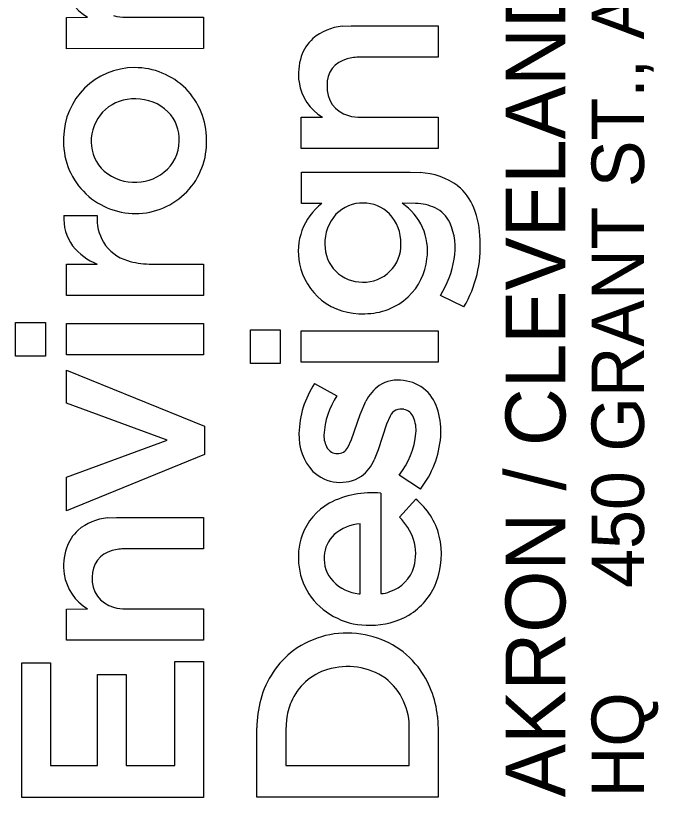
# Model space of a CAD drawing. Extents: x -13.5 to 34, y 0 to 22.
# Drawn here: x 32.377 to 32.989, y 3.138 to 3.882 of the extents above; entities that cross this region are included whole.
import ezdxf

# ---------------------------------------------------------------- set-up
doc = ezdxf.new("R2010")
doc.units = 0
doc.layers.add('RW_X_CL_100_Bearings', color=7, linetype='Continuous')

msp = doc.modelspace()

# ---------------------------------------------------------------- linework, layer by layer
at = {"layer": 'RW_X_CL_100_Bearings'}
for p, q in [((32.42542, 3.88066), (32.44552, 3.88071)), ((32.42542, 3.85086), (32.42542, 3.88066)), ((32.48222, 3.88071), (32.55569, 3.88071)), ((32.55569, 3.88071), (32.55571, 3.85096)), ((32.68784, 3.8722), (32.69634, 3.87266)), ((32.69634, 3.87266), (32.77916, 3.87266)), ((32.77916, 3.87266), (32.77917, 3.84287)), ((32.55571, 3.85096), (32.42542, 3.85086)), ((32.77917, 3.84287), (32.70485, 3.8428)), ((32.64888, 3.7855), (32.66897, 3.78555)), ((32.64888, 3.75569), (32.64888, 3.7855)), ((32.70568, 3.78555), (32.77915, 3.78555)), ((32.77915, 3.78555), (32.77917, 3.75579)), ((32.77917, 3.75579), (32.64888, 3.75569)), ((32.6489, 3.70336), (32.64889, 3.73322)), ((32.64889, 3.73322), (32.75236, 3.73322)), ((32.75236, 3.73322), (32.76191, 3.73285)), ((32.66836, 3.70336), (32.6489, 3.70336)), ((32.75763, 3.70356), (32.74487, 3.70361)), ((32.42299, 3.69193), (32.45454, 3.69193)), ((32.42542, 3.64577), (32.45473, 3.64579)), ((32.42542, 3.61593), (32.42542, 3.64577)), ((32.50413, 3.64581), (32.55571, 3.64573)), ((32.55571, 3.64573), (32.55565, 3.61593)), ((32.55565, 3.61593), (32.42542, 3.61593)), ((32.8036, 3.60491), (32.7812, 3.61598)), ((32.37705, 3.55818), (32.37705, 3.59026)), ((32.37705, 3.59026), (32.40543, 3.59026)), ((32.40543, 3.59026), (32.40543, 3.55818)), ((32.42542, 3.55942), (32.42542, 3.58928)), ((32.42542, 3.58928), (32.55571, 3.58928)), ((32.55571, 3.58928), (32.55571, 3.55942)), ((32.60051, 3.55111), (32.60051, 3.58319)), ((32.60051, 3.58319), (32.62889, 3.58319)), ((32.62889, 3.58319), (32.62889, 3.55111)), ((32.64888, 3.55234), (32.64888, 3.5822)), ((32.64888, 3.5822), (32.77917, 3.5822)), ((32.77917, 3.5822), (32.77917, 3.55234)), ((32.55571, 3.55942), (32.42542, 3.55942)), ((32.40543, 3.55818), (32.37705, 3.55818)), ((32.62889, 3.55111), (32.60051, 3.55111)), ((32.77917, 3.55234), (32.64888, 3.55234)), ((32.42542, 3.51327), (32.42542, 3.5446)), ((32.42542, 3.5446), (32.5567, 3.4913)), ((32.66151, 3.53207), (32.68268, 3.52025)), ((32.70483, 3.50258), (32.71036, 3.51526)), ((32.52117, 3.47798), (32.42542, 3.51327)), ((32.69675, 3.47868), (32.70483, 3.50258)), ((32.73342, 3.50101), (32.72985, 3.4933)), ((32.5567, 3.4913), (32.5567, 3.46441)), ((32.72985, 3.4933), (32.72213, 3.46882)), ((32.42542, 3.44294), (32.52117, 3.47798)), ((32.69299, 3.47117), (32.69675, 3.47868)), ((32.5567, 3.46441), (32.42542, 3.41086)), ((32.72213, 3.46882), (32.71822, 3.45921)), ((32.42542, 3.41086), (32.42542, 3.44294)), ((32.76214, 3.43141), (32.74198, 3.44469)), ((32.72453, 3.42747), (32.72463, 3.33195)), ((32.74228, 3.40465), (32.75768, 3.422)), ((32.46439, 3.40397), (32.47289, 3.40443)), ((32.47289, 3.40443), (32.55571, 3.40443)), ((32.55571, 3.40443), (32.55571, 3.37465)), ((32.70489, 3.33182), (32.70489, 3.39834)), ((32.55571, 3.37465), (32.4814, 3.37457)), ((32.70361, 3.33165), (32.70489, 3.33182)), ((32.42542, 3.31728), (32.44552, 3.31733)), ((32.42542, 3.28747), (32.42542, 3.31728)), ((32.48222, 3.31733), (32.55569, 3.31733)), ((32.55569, 3.31733), (32.55571, 3.28756)), ((32.55571, 3.28756), (32.42542, 3.28747)), ((32.38298, 3.13791), (32.38298, 3.26598)), ((32.38298, 3.26598), (32.41012, 3.26598)), ((32.41012, 3.26598), (32.41012, 3.16827)), ((32.52857, 3.16827), (32.52857, 3.26722)), ((32.52857, 3.26722), (32.55571, 3.26722)), ((32.55571, 3.26722), (32.55571, 3.13791)), ((32.45503, 3.16827), (32.45503, 3.25488)), ((32.45503, 3.25488), (32.48218, 3.25488)), ((32.48218, 3.25488), (32.48218, 3.16827)), ((32.63465, 3.21178), (32.63407, 3.2023)), ((32.77847, 3.21497), (32.77917, 3.2021)), ((32.60643, 3.13799), (32.60644, 3.204)), ((32.63407, 3.2023), (32.63407, 3.16838)), ((32.75149, 3.16834), (32.75153, 3.20239)), ((32.77917, 3.2021), (32.77917, 3.138)), ((32.41012, 3.16827), (32.45503, 3.16827)), ((32.48218, 3.16827), (32.52857, 3.16827)), ((32.63407, 3.16838), (32.75149, 3.16834)), ((32.55571, 3.13791), (32.38298, 3.13791)), ((32.77917, 3.138), (32.60643, 3.13799))]:
    msp.add_line(p, q, dxfattribs=at)
for points in [[(32.42542, 3.85086), (32.42542, 3.88066), (32.44552, 3.88071)], [(32.48222, 3.88071), (32.55569, 3.88071), (32.55571, 3.85096), (32.42542, 3.85086)], [(32.68784, 3.8722), (32.69634, 3.87266), (32.77916, 3.87266), (32.77917, 3.84287), (32.70485, 3.8428)], [(32.64888, 3.75569), (32.64888, 3.7855), (32.66897, 3.78555)], [(32.70568, 3.78555), (32.77915, 3.78555), (32.77917, 3.75579), (32.64888, 3.75569)], [(32.66836, 3.70336), (32.6489, 3.70336), (32.64889, 3.73322), (32.75236, 3.73322), (32.76191, 3.73285)], [(32.75763, 3.70356), (32.74487, 3.70361)], [(32.42299, 3.69193), (32.45454, 3.69193)], [(32.50413, 3.64581), (32.55571, 3.64573), (32.55565, 3.61593), (32.42542, 3.61593)], [(32.42542, 3.61593), (32.42542, 3.64577), (32.45473, 3.64579)], [(32.8036, 3.60491), (32.7812, 3.61598)], [(32.66151, 3.53207), (32.68268, 3.52025)], [(32.69299, 3.47117), (32.69675, 3.47868), (32.70483, 3.50258), (32.71036, 3.51526)], [(32.73342, 3.50101), (32.72985, 3.4933), (32.72213, 3.46882), (32.71822, 3.45921)], [(32.76214, 3.43141), (32.74198, 3.44469)], [(32.72453, 3.42747), (32.72463, 3.33195)], [(32.74228, 3.40465), (32.75768, 3.422)], [(32.46439, 3.40397), (32.47289, 3.40443), (32.55571, 3.40443), (32.55571, 3.37465), (32.4814, 3.37457)], [(32.70361, 3.33165), (32.70489, 3.33182), (32.70489, 3.39834)], [(32.42542, 3.28747), (32.42542, 3.31728), (32.44552, 3.31733)], [(32.48222, 3.31733), (32.55569, 3.31733), (32.55571, 3.28756), (32.42542, 3.28747)], [(32.77847, 3.21497), (32.77917, 3.2021), (32.77917, 3.138), (32.60643, 3.13799)], [(32.63465, 3.21178), (32.63407, 3.2023), (32.63407, 3.16838), (32.75149, 3.16834), (32.75153, 3.20239)], [(32.60643, 3.13799), (32.60644, 3.204)]]:
    msp.add_lwpolyline(points, dxfattribs=at)
for points in [[(32.37705, 3.55818), (32.37705, 3.59026), (32.40543, 3.59026), (32.40543, 3.55818)], [(32.42542, 3.55942), (32.42542, 3.58928), (32.55571, 3.58928), (32.55571, 3.55942)], [(32.60051, 3.55111), (32.60051, 3.58319), (32.62889, 3.58319), (32.62889, 3.55111)], [(32.64888, 3.55234), (32.64888, 3.5822), (32.77917, 3.5822), (32.77917, 3.55234)], [(32.42542, 3.41086), (32.42542, 3.44294), (32.52117, 3.47798), (32.42542, 3.51327), (32.42542, 3.5446), (32.5567, 3.4913), (32.5567, 3.46441)], [(32.38298, 3.13791), (32.38298, 3.26598), (32.41012, 3.26598), (32.41012, 3.16827), (32.45503, 3.16827), (32.45503, 3.25488), (32.48218, 3.25488), (32.48218, 3.16827), (32.52857, 3.16827), (32.52857, 3.26722), (32.55571, 3.26722), (32.55571, 3.13791)]]:
    msp.add_lwpolyline(points, close=True, dxfattribs=at)
for centre, radius, start, end in [((32.47027, 3.92141), 0.04763, 188.96462, 238.69865), ((32.47027, 3.92141), 0.04763, 188.96462, 238.69865), ((32.48183, 3.92286), 0.04215, 254.08913, 270.52838), ((32.48183, 3.92286), 0.04215, 254.08913, 270.52838), ((32.69216, 3.82251), 0.04988, 94.97056, 130.22484), ((32.69216, 3.82251), 0.04988, 94.97056, 130.22484), ((32.68694, 3.83085), 0.04016, 132.22383, 161.68229), ((32.68694, 3.83085), 0.04016, 132.22383, 161.68229), ((32.70217, 3.82642), 0.05602, 162.27398, 187.79173), ((32.70217, 3.82642), 0.05602, 162.27398, 187.79173), ((32.70453, 3.79679), 0.04601, 89.60515, 105.33026), ((32.70453, 3.79679), 0.04601, 89.60515, 105.33026), ((32.69828, 3.81689), 0.02498, 103.68683, 182.21395), ((32.69828, 3.81689), 0.02498, 103.68683, 182.21395), ((32.49014, 3.76543), 0.0674, 89.84756, 179.64047), ((32.49014, 3.76543), 0.0674, 89.84756, 179.64047), ((32.49057, 3.76474), 0.0681, 359.54009, 90.21138), ((32.49057, 3.76474), 0.0681, 359.54009, 90.21138), ((32.69372, 3.82624), 0.04763, 188.96462, 238.69865), ((32.69372, 3.82624), 0.04763, 188.96462, 238.69865), ((32.7008, 3.81381), 0.02757, 175.58441, 255.13816), ((32.7008, 3.81381), 0.02757, 175.58441, 255.13816), ((32.48923, 3.76263), 0.0404, 87.04809, 175.57259), ((32.48923, 3.76263), 0.0404, 87.04809, 175.57259), ((32.49204, 3.75999), 0.04299, 45.84264, 90.98008), ((32.49204, 3.75999), 0.04299, 45.84264, 90.98008), ((32.49458, 3.76421), 0.03821, 357.88569, 44.15902), ((32.49458, 3.76421), 0.03821, 357.88569, 44.15902), ((32.70529, 3.82769), 0.04215, 254.08913, 270.52838), ((32.70529, 3.82769), 0.04215, 254.08913, 270.52838), ((32.49083, 3.76209), 0.06819, 176.8344, 270.40384), ((32.49083, 3.76209), 0.06819, 176.8344, 270.40384), ((32.48729, 3.7625), 0.03848, 175.15378, 221.14706), ((32.48729, 3.7625), 0.03848, 175.15378, 221.14706), ((32.49123, 3.76139), 0.06749, 270.06243, 2.37759), ((32.49123, 3.76139), 0.06749, 270.06243, 2.37759), ((32.49446, 3.76318), 0.0383, 308.28936, 359.43468), ((32.49446, 3.76318), 0.0383, 308.28936, 359.43468), ((32.48919, 3.76607), 0.04228, 223.09994, 268.80895), ((32.48919, 3.76607), 0.04228, 223.09994, 268.80895), ((32.49096, 3.7679), 0.04418, 266.56515, 308.06078), ((32.49096, 3.7679), 0.04418, 266.56515, 308.06078), ((32.75907, 3.66789), 0.06503, 53.40344, 87.49062), ((32.75907, 3.66789), 0.06503, 53.40344, 87.49062), ((32.76517, 3.68039), 0.05141, 21.60748, 50.5577), ((32.76517, 3.68039), 0.05141, 21.60748, 50.5577), ((32.70292, 3.65813), 0.05692, 127.37482, 192.22468), ((32.70292, 3.65813), 0.05692, 127.37482, 192.22468), ((32.70693, 3.66927), 0.0346, 88.47302, 136.42562), ((32.70693, 3.66927), 0.0346, 88.47302, 136.42562), ((32.70814, 3.66963), 0.03424, 44.27195, 90.47623), ((32.70814, 3.66963), 0.03424, 44.27195, 90.47623), ((32.71421, 3.65829), 0.05472, 352.1125, 55.92295), ((32.71421, 3.65829), 0.05472, 352.1125, 55.92295), ((32.75666, 3.65725), 0.04633, 65.01687, 88.8011), ((32.75666, 3.65725), 0.04633, 65.01687, 88.8011), ((32.71141, 3.66602), 0.0401, 137.46739, 182.33237), ((32.71141, 3.66602), 0.0401, 137.46739, 182.33237), ((32.70368, 3.666), 0.03996, 358.57141, 43.53765), ((32.70368, 3.666), 0.03996, 358.57141, 43.53765), ((32.7626, 3.67155), 0.03085, 26.26808, 63.80301), ((32.7626, 3.67155), 0.03085, 26.26808, 63.80301), ((32.73069, 3.66714), 0.08835, 1.15143, 21.3627), ((32.73069, 3.66714), 0.08835, 1.15143, 21.3627), ((32.46616, 3.68882), 0.04329, 175.87313, 216.34747), ((32.46616, 3.68882), 0.04329, 175.87313, 216.34747), ((32.50087, 3.68948), 0.04639, 176.9688, 209.60636), ((32.50087, 3.68948), 0.04639, 176.9688, 209.60636), ((32.73565, 3.66154), 0.05953, 349.30734, 23.43071), ((32.73565, 3.66154), 0.05953, 349.30734, 23.43071), ((32.47466, 3.69716), 0.05511, 218.09809, 248.7907), ((32.47466, 3.69716), 0.05511, 218.09809, 248.7907), ((32.49514, 3.68814), 0.04079, 211.94466, 253.2028), ((32.49514, 3.68814), 0.04079, 211.94466, 253.2028), ((32.70645, 3.6637), 0.03511, 178.88208, 271.08374), ((32.70645, 3.6637), 0.03511, 178.88208, 271.08374), ((32.70818, 3.66404), 0.03546, 268.27882, 1.55016), ((32.70818, 3.66404), 0.03546, 268.27882, 1.55016), ((32.70538, 3.66244), 0.11383, 329.6388, 3.25998), ((32.70538, 3.66244), 0.11383, 329.6388, 3.25998), ((32.50465, 3.7165), 0.07069, 252.46555, 269.57296), ((32.50465, 3.7165), 0.07069, 252.46555, 269.57296), ((32.70988, 3.65708), 0.05887, 313.74196, 353.8554), ((32.70988, 3.65708), 0.05887, 313.74196, 353.8554), ((32.70738, 3.66334), 0.08771, 327.31495, 351.57478), ((32.70738, 3.66334), 0.08771, 327.31495, 351.57478), ((32.70463, 3.65696), 0.05837, 190.75182, 231.28919), ((32.70463, 3.65696), 0.05837, 190.75182, 231.28919), ((32.70632, 3.66112), 0.06269, 232.46061, 272.59022), ((32.70632, 3.66112), 0.06269, 232.46061, 272.59022), ((32.70954, 3.65901), 0.06051, 269.6361, 312.70877), ((32.70954, 3.65901), 0.06051, 269.6361, 312.70877), ((32.73636, 3.48258), 0.08973, 146.53104, 178.7571), ((32.73636, 3.48258), 0.08973, 146.53104, 178.7571), ((32.74661, 3.49713), 0.04053, 125.51182, 153.41595), ((32.74661, 3.49713), 0.04053, 125.51182, 153.41595), ((32.7406, 3.5026), 0.03263, 80.17192, 122.51969), ((32.7406, 3.5026), 0.03263, 80.17192, 122.51969), ((32.74278, 3.49824), 0.03667, 47.79344, 84.68918), ((32.74278, 3.49824), 0.03667, 47.79344, 84.68918), ((32.73788, 3.4946), 0.04267, 14.9966, 46.20632), ((32.73788, 3.4946), 0.04267, 14.9966, 46.20632), ((32.74519, 3.4789), 0.07495, 146.51121, 176.91007), ((32.74519, 3.4789), 0.07495, 146.51121, 176.91007), ((32.74384, 3.49631), 0.01143, 76.66094, 155.7053), ((32.74384, 3.49631), 0.01143, 76.66094, 155.7053), ((32.74397, 3.49511), 0.01256, 21.5098, 78.52618), ((32.74397, 3.49511), 0.01256, 21.5098, 78.52618), ((32.72592, 3.48766), 0.03209, 354.57264, 22.06805), ((32.72592, 3.48766), 0.03209, 354.57264, 22.06805), ((32.71044, 3.48674), 0.07121, 355.83062, 15.39138), ((32.71044, 3.48674), 0.07121, 355.83062, 15.39138), ((32.69666, 3.48238), 0.05005, 177.53659, 222.79318), ((32.69666, 3.48238), 0.05005, 177.53659, 222.79318), ((32.68248, 3.49149), 0.0757, 321.81101, 354.79685), ((32.68248, 3.49149), 0.0757, 321.81101, 354.79685), ((32.6931, 3.48233), 0.02276, 178.47474, 211.08679), ((32.6931, 3.48233), 0.02276, 178.47474, 211.08679), ((32.68952, 3.4882), 0.09219, 321.9777, 355.87384), ((32.68952, 3.4882), 0.09219, 321.9777, 355.87384), ((32.68331, 3.4767), 0.01148, 212.23676, 268.37769), ((32.68331, 3.4767), 0.01148, 212.23676, 268.37769), ((32.68342, 3.47589), 0.01067, 267.71603, 333.73375), ((32.68342, 3.47589), 0.01067, 267.71603, 333.73375), ((32.68098, 3.4758), 0.04077, 308.08772, 335.98736), ((32.68098, 3.4758), 0.04077, 308.08772, 335.98736), ((32.68599, 3.47535), 0.0375, 225.98539, 302.47965), ((32.68599, 3.47535), 0.0375, 225.98539, 302.47965), ((32.7152, 3.34414), 0.08384, 83.61499, 118.28755), ((32.7152, 3.34414), 0.08384, 83.61499, 118.28755), ((32.70239, 3.36906), 0.05583, 118.83082, 160.62438), ((32.70239, 3.36906), 0.05583, 118.83082, 160.62438), ((32.71744, 3.37167), 0.06443, 13.53365, 51.36148), ((32.71744, 3.37167), 0.06443, 13.53365, 51.36148), ((32.46871, 3.35428), 0.04988, 94.96958, 130.22249), ((32.46871, 3.35428), 0.04988, 94.96958, 130.22249), ((32.70378, 3.36556), 0.05486, 19.03571, 45.44059), ((32.70378, 3.36556), 0.05486, 19.03571, 45.44059), ((32.70785, 3.35609), 0.04235, 94.00805, 130.88169), ((32.70785, 3.35609), 0.04235, 94.00805, 130.88169), ((32.46348, 3.36263), 0.04015, 132.22192, 161.68183), ((32.46348, 3.36263), 0.04015, 132.22192, 161.68183), ((32.71041, 3.36612), 0.06437, 160.52012, 215.78311), ((32.71041, 3.36612), 0.06437, 160.52012, 215.78311), ((32.70048, 3.36628), 0.02985, 132.98507, 177.179), ((32.70048, 3.36628), 0.02985, 132.98507, 177.179), ((32.71069, 3.3697), 0.047, 344.60586, 17.007), ((32.71069, 3.3697), 0.047, 344.60586, 17.007), ((32.70635, 3.36921), 0.07579, 339.3542, 13.37853), ((32.70635, 3.36921), 0.07579, 339.3542, 13.37853), ((32.47872, 3.35819), 0.05601, 162.27355, 187.79185), ((32.47872, 3.35819), 0.05601, 162.27355, 187.79185), ((32.47482, 3.34867), 0.02498, 103.68646, 182.21874), ((32.47482, 3.34867), 0.02498, 103.68646, 182.21874), ((32.48108, 3.32856), 0.04601, 89.60494, 105.3284), ((32.48108, 3.32856), 0.04601, 89.60494, 105.3284), ((32.7017, 3.36503), 0.03115, 175.00126, 223.28301), ((32.7017, 3.36503), 0.03115, 175.00126, 223.28301), ((32.47026, 3.35802), 0.04762, 188.96199, 238.70369), ((32.47026, 3.35802), 0.04762, 188.96199, 238.70369), ((32.7224, 3.36715), 0.03504, 288.00773, 343.55078), ((32.7224, 3.36715), 0.03504, 288.00773, 343.55078), ((32.47735, 3.34558), 0.02756, 175.58538, 255.14386), ((32.47735, 3.34558), 0.02756, 175.58538, 255.14386), ((32.70891, 3.37363), 0.04231, 225.06188, 262.79738), ((32.70891, 3.37363), 0.04231, 225.06188, 262.79738), ((32.71894, 3.3652), 0.0626, 300.94269, 338.73225), ((32.71894, 3.3652), 0.0626, 300.94269, 338.73225), ((32.71253, 3.37054), 0.06872, 217.74516, 271.65431), ((32.71253, 3.37054), 0.06872, 217.74516, 271.65431), ((32.72474, 3.35216), 0.02021, 269.7003, 294.8711), ((32.72474, 3.35216), 0.02021, 269.7003, 294.8711), ((32.48183, 3.35948), 0.04215, 254.09162, 270.52835), ((32.48183, 3.35948), 0.04215, 254.09162, 270.52835), ((32.71549, 3.37241), 0.07056, 269.20477, 300.33412), ((32.71549, 3.37241), 0.07056, 269.20477, 300.33412), ((32.69229, 3.20792), 0.08641, 81.19402, 125.99844), ((32.69229, 3.20792), 0.08641, 81.19402, 125.99844), ((32.69458, 3.21132), 0.08272, 37.85208, 82.40204), ((32.69458, 3.21132), 0.08272, 37.85208, 82.40204), ((32.69387, 3.20893), 0.08654, 127.23621, 165.14796), ((32.69387, 3.20893), 0.08654, 127.23621, 165.14796), ((32.69279, 3.19862), 0.06389, 55.67272, 107.20935), ((32.69279, 3.19862), 0.06389, 55.67272, 107.20935), ((32.68586, 3.20567), 0.09308, 5.73329, 37.30396), ((32.68586, 3.20567), 0.09308, 5.73329, 37.30396), ((32.68893, 3.20782), 0.05398, 106.18808, 157.38609), ((32.68893, 3.20782), 0.05398, 106.18808, 157.38609), ((32.69291, 3.20499), 0.05867, 357.46616, 52.26647), ((32.69291, 3.20499), 0.05867, 357.46616, 52.26647), ((32.71426, 3.20281), 0.10783, 164.7861, 179.37039), ((32.71426, 3.20281), 0.10783, 164.7861, 179.37039), ((32.69829, 3.20389), 0.06412, 157.35705, 172.92755), ((32.69829, 3.20389), 0.06412, 157.35705, 172.92755)]:
    msp.add_arc(centre, radius, start, end, dxfattribs=at)

# ---------------------------------------------------------------- texts
for s, height, p in [('450 GRANT ST., AKRON, OH  44311', 0.0498462, (32.97489, 3.33738)), ('AKRON / CLEVELAND / COLUMBUS', 0.056969, (32.90012, 3.138)), ('HQ ', 0.049846, (32.97489, 3.138))]:
    msp.add_text(s, height=height, rotation=90, dxfattribs=at).set_placement(p)

doc.saveas('drawing.dxf')
